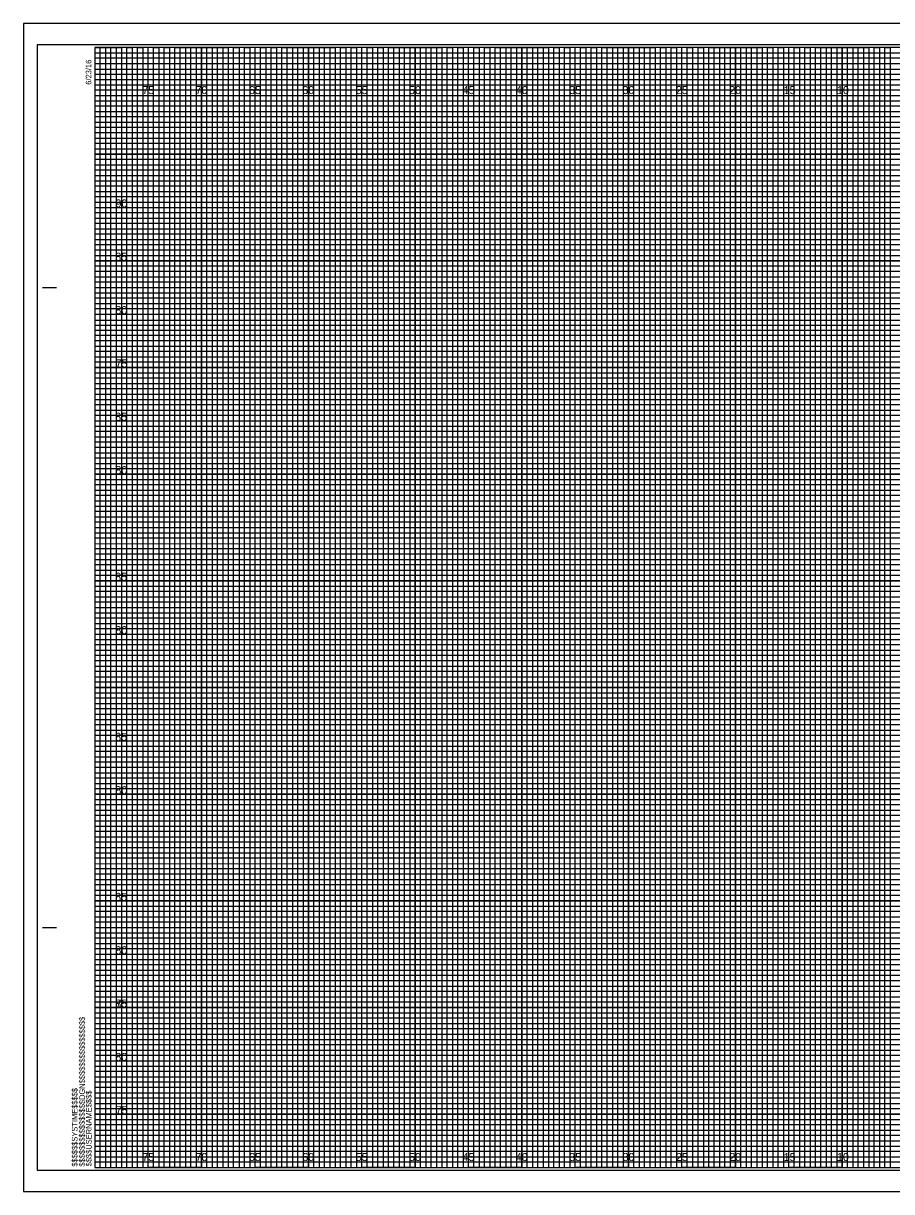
# Model space of a CAD drawing. Extents: x -7 to 182, y -2 to 1647.
# Drawn here: x -6.7 to 74.6, y 107.7 to 217.2 of the extents above; entities that cross this region are included whole.
import ezdxf

# ---------------------------------------------------------------- set-up
doc = ezdxf.new("R2010")
doc.units = 0
for name, color, linetype in [('Exist Cross Section Cell', 7, 'Continuous'), ('Exist XS Ground Line', 7, 'Continuous'), ('Prop CMT Pvmt Course 3', 7, 'Continuous'), ('Prop CMT Pvmt Wedge Surface 1', 7, 'Continuous'), ('Prop CMT Pvmt Wedge Surface 2', 7, 'Continuous'), ('Prop CMT Pvmt Wedge Surface 3', 7, 'Continuous'), ('Prop CMT Shld Paved Course 1', 7, 'Continuous'), ('Prop CMT Shld Paved Course 2', 7, 'Continuous'), ('Prop CMT Shld Paved Course 3', 7, 'Continuous'), ('Prop CMT Slope Grass', 7, 'Continuous'), ('Prop CMT Subgrade Earthwork', 7, 'Continuous')]:
    doc.layers.add(name, color=color, linetype=linetype)

msp = doc.modelspace()

# ---------------------------------------------------------------- linework, layer by layer
at = {"layer": 'Exist XS Ground Line'}
for p, q in [((5, 215), (0, 215)), ((5, 110), (5, 215)), ((15, 215), (10, 215)), ((10, 215), (10, 110)), ((15, 110), (15, 215)), ((25, 215), (20, 215)), ((20, 215), (20, 110)), ((25, 110), (25, 215)), ((35, 215), (30, 215)), ((30, 215), (30, 110)), ((35, 110), (35, 215)), ((45, 215), (40, 215)), ((40, 215), (40, 110)), ((45, 110), (45, 215)), ((55, 215), (50, 215)), ((50, 215), (50, 110)), ((55, 110), (55, 215)), ((65, 215), (60, 215)), ((60, 215), (60, 110)), ((65, 110), (65, 215)), ((75, 215), (70, 215)), ((70, 215), (70, 110)), ((10, 110), (5, 110)), ((20, 110), (15, 110)), ((30, 110), (25, 110)), ((40, 110), (35, 110)), ((50, 110), (45, 110)), ((60, 110), (55, 110)), ((70, 110), (65, 110))]:
    msp.add_line(p, q, dxfattribs=at)
for points in [[(0, 210), (160, 210), (160, 205), (0, 205)], [(0, 200), (160, 200), (160, 195), (0, 195)], [(0, 190), (160, 190), (160, 185), (0, 185)], [(0, 180), (160, 180), (160, 175), (0, 175)], [(0, 170), (160, 170), (160, 165), (0, 165)], [(0, 160), (160, 160), (160, 155), (0, 155)], [(0, 150), (160, 150), (160, 145), (0, 145)], [(0, 140), (160, 140), (160, 135), (0, 135)], [(0, 130), (160, 130), (160, 125), (0, 125)], [(0, 120), (160, 120), (160, 115), (0, 115)]]:
    msp.add_lwpolyline(points, dxfattribs=at)
at = {"layer": 'Prop CMT Pvmt Course 3'}
msp.add_lwpolyline([(-6.7, 107.75), (161.65, 107.75), (161.65, 217.25), (-6.7, 217.25)], close=True, dxfattribs=at)
at = {"layer": 'Prop CMT Pvmt Wedge Surface 1'}
for p, q in [((0, 214.5), (130, 214.5)), ((130, 213.99), (0, 213.99)), ((0, 213.99), (0, 213.5)), ((0, 213.5), (130, 213.5)), ((130, 212.94), (0, 212.94)), ((0, 212.94), (0, 212)), ((0, 212), (160, 212))]:
    msp.add_line(p, q, dxfattribs=at)
for points in [[(0, 211.5), (135, 211.5), (160, 211.5), (160, 211), (0, 211)], [(0, 210.5), (160, 210.5), (160, 209.5), (0, 209.5)], [(0, 209), (160, 209), (160, 208.5), (0, 208.49)], [(0, 208), (160, 208), (160, 207), (0, 207)], [(0, 206.5), (160, 206.5), (160, 206), (0, 206)], [(0, 205.5), (160, 205.5), (160, 204.5), (0, 204.5)], [(0, 204), (160, 204), (160, 203.5), (0, 203.5)], [(0, 203), (160, 203), (160, 202), (0, 202)], [(0, 201.5), (160, 201.5), (160, 201), (0, 201)], [(0, 200.5), (160, 200.5), (160, 199.5), (0, 199.5)], [(0, 199), (160, 199), (160, 198.5), (0, 198.5)], [(0, 198), (160, 198), (160, 196.97), (160, 196.5), (160, 196), (0, 196)], [(0, 197), (160, 197), (160, 196.5), (0, 196.5)], [(0, 195.5), (160, 195.5), (160, 194.5), (0, 194.52)], [(0, 194.52), (160, 194.5), (160, 194), (0, 194)], [(0, 193.5), (160, 193.5), (160, 193), (0, 193)], [(0, 192), (160, 192), (160, 191.5), (0, 191.5)], [(0, 191), (160, 191), (160, 190.5), (0, 190.5)], [(-0.04, 189.44), (160, 189.44), (160, 188.94), (-0.04, 188.94)], [(0, 188.5), (160, 188.5), (160, 188), (0, 188)], [(0, 187), (160, 187), (160, 186.5), (0, 186.5)], [(0, 186), (160, 186), (160, 185.5), (0, 185.5)], [(0, 184.5), (160, 184.5), (160, 184), (0, 184)], [(0, 183.5), (160, 183.5), (160, 183), (0, 183)], [(0, 182), (160, 182), (160, 181.5), (0, 181.5)], [(0, 181), (160, 181), (160, 180.5), (0, 180.5)], [(0, 179.5), (160, 179.5), (160, 178.99), (0, 179)], [(0, 178.5), (160, 178.5), (160, 178), (0, 178)], [(0, 177), (160, 177), (160, 176.5), (0, 176.5)], [(0, 176), (160, 176), (160, 175.5), (0, 175.5)], [(0, 174.5), (160, 174.5), (160, 174), (0, 174)], [(0, 173.5), (160, 173.5), (160, 173), (0, 173)], [(0, 172), (160, 172), (160, 171.5), (0, 171.5)], [(0, 171), (160, 171), (160, 170.5), (0, 170.5)], [(0, 169.5), (160, 169.5), (160, 169), (0, 169)], [(0, 168.5), (160.03, 168.46), (160, 168), (0, 168)], [(0, 167), (160, 167), (160, 166.5), (0, 166.5)], [(0, 166), (160, 166), (160, 165.5), (0, 165.5)], [(0, 164.5), (160, 164.5), (160, 164), (0, 164)], [(0, 163.5), (160, 163.5), (160, 163), (0, 163)], [(0, 162), (160, 162), (160, 161.5), (0, 161.5)], [(0, 161), (160, 161), (160, 160.5), (0, 160.5)], [(0, 159.5), (160, 159.5), (160, 159), (0, 159)], [(0, 158.5), (160, 158.5), (160, 158), (0, 158)], [(0, 157), (160, 157), (160, 156.5), (0, 156.5)], [(0, 156), (160, 156), (160, 155.5), (0, 155.5)], [(0, 154.5), (160, 154.5), (160, 154), (0, 154)], [(0, 153.5), (160, 153.5), (160, 153), (0, 153)], [(0, 152), (160, 152), (160, 151.5), (0, 151.5)], [(0, 151), (160, 151), (160, 150.5), (0, 150.5)], [(0, 149.5), (160, 149.5), (160, 148.99), (0, 149)], [(0, 148.5), (160, 148.5), (160, 148), (0, 148)], [(0, 147), (160, 147), (160, 146.5), (0, 146.5)], [(0, 146), (160, 146), (160, 145.5), (0, 145.5)], [(0, 144.5), (160, 144.5), (160, 144), (0, 144)], [(0, 143.5), (160, 143.5), (160, 143), (0, 143)], [(0, 142), (160, 142), (160, 141.5), (0, 141.5)], [(0, 141), (160, 141), (160, 140.5), (0, 140.5)], [(0, 139.5), (160, 139.5), (160, 139), (0, 139)], [(0, 138.5), (160.03, 138.46), (160, 138), (0, 138)], [(0, 137), (160, 137), (160, 136.5), (0, 136.5)], [(0, 136), (160, 136), (160, 135.5), (0, 135.5)], [(0, 134.5), (160, 134.5), (160, 134), (0, 134)], [(0, 133.5), (160, 133.5), (160, 133), (0, 133)], [(0, 132), (160, 132), (160, 131.5), (0, 131.5)], [(0, 131), (160, 131), (160, 130.5), (0, 130.5)], [(0, 129.5), (160, 129.5), (160, 129), (0, 129)], [(0, 128.5), (160, 128.5), (160, 128), (0, 128)], [(0, 127), (160, 127), (160, 126.5), (0, 126.5)], [(0, 126), (160, 126), (160, 125.5), (0, 125.5)], [(0, 124.5), (160, 124.5), (160, 124), (0, 124)], [(0, 123.5), (160, 123.5), (160, 123), (0, 123)], [(0, 122), (160, 122), (160, 121.5), (0, 121.5)], [(0, 121), (160, 121), (160, 120.5), (0, 120.5)], [(0, 119.5), (160, 119.5), (160, 119), (0, 119)], [(0, 118.5), (160, 118.5), (160, 118), (0, 118)], [(0, 117), (160, 117), (160, 116.5), (0, 116.5)], [(0, 116), (160, 116), (160, 115.5), (0, 115.5)], [(0, 114.5), (160, 114.5), (160, 114), (0, 114)], [(0, 113.5), (160, 113.5), (160, 113), (0, 113)], [(0, 112), (160, 112), (160, 111.5), (0, 111.5)], [(0, 111), (160, 111), (160, 110.5), (0, 110.5)]]:
    msp.add_lwpolyline(points, dxfattribs=at)
at = {"layer": 'Prop CMT Pvmt Wedge Surface 2'}
for p, q in [((-4.9, 192.5), (-3.65, 192.5)), ((-4.85, 192.5), (-3.6, 192.5)), ((-4.9, 132.5), (-3.65, 132.5)), ((-4.85, 132.5), (-3.6, 132.5)), ((0, 110), (0, 110)), ((0, 110), (0, 110)), ((0, 110), (0, 110)), ((0, 110), (0, 110)), ((0, 110), (0, 110)), ((0, 110), (0, 110)), ((0, 110), (0, 110))]:
    msp.add_line(p, q, dxfattribs=at)
msp.add_lwpolyline([(160, 215), (0, 215), (0, 110), (160, 110)], close=True, dxfattribs=at)
at = {"layer": 'Prop CMT Pvmt Wedge Surface 3'}
for points in [[(0, 110), (0.5, 110), (0.5, 215), (1, 215), (1, 110)], [(1, 110), (1.5, 110), (1.5, 215), (2, 215), (2, 110)], [(2.5, 110), (3, 110), (3, 215), (3.5, 215), (3.5, 110)], [(3.5, 110), (4, 110), (4, 215), (4.5, 215), (4.5, 110)], [(5, 110), (5.5, 110), (5.5, 215), (6, 215), (6, 110)], [(6, 110), (6.5, 110), (6.5, 215), (7, 215), (7, 110)], [(7.5, 110), (8, 110), (8, 215), (8.5, 215), (8.5, 110)], [(8.5, 110), (9, 110), (9, 215), (9.5, 215), (9.5, 110)], [(10, 110), (10.5, 110), (10.5, 215), (11, 215), (11, 110)], [(11, 110), (11.5, 110), (11.5, 215), (12, 215), (12, 110)], [(12.5, 110), (13, 110), (13, 215), (13.5, 215), (13.5, 110)], [(13.5, 110), (14, 110), (14, 215), (14.5, 215), (14.5, 110)], [(15, 110), (15.5, 110), (15.5, 215), (16, 215), (16, 110)], [(16, 110), (16.5, 110), (16.5, 215), (17, 215), (17, 110)], [(17.5, 110), (18, 110), (18, 215), (18.5, 215), (18.5, 110)], [(18.5, 110), (19, 110), (19, 215), (19.5, 215), (19.5, 110)], [(20, 110), (20.5, 110), (20.5, 215), (21, 215), (21, 110)], [(21, 110), (21.5, 110), (21.5, 215), (22, 215), (22, 110)], [(22.5, 110), (23, 110), (23, 215), (23.5, 215), (23.5, 110)], [(23.5, 110), (24, 110), (24, 215), (24.5, 215), (24.5, 110)], [(25, 110), (25.5, 110), (25.5, 215), (26, 215), (26, 110)], [(26, 110), (26.5, 110), (26.5, 215), (27, 215), (27, 110)], [(27.5, 110), (28, 110), (28, 215), (28.5, 215), (28.5, 110)], [(28.5, 110), (29, 110), (29, 215), (29.5, 215), (29.5, 110)], [(30, 110), (30.5, 110), (30.5, 215), (31, 215), (31, 110)], [(31, 110), (31.5, 110), (31.5, 215), (32, 215), (32, 110)], [(32.5, 110), (33, 110), (33, 215), (33.5, 215), (33.5, 110)], [(33.5, 110), (34, 110), (34, 215), (34.5, 215), (34.5, 110)], [(35, 110), (35.5, 110), (35.5, 215), (36, 215), (36, 110)], [(36, 110), (36.5, 110), (36.5, 215), (37, 215), (37, 110)], [(37.5, 110), (38, 110), (38, 215), (38.5, 215), (38.5, 110)], [(38.5, 110), (39, 110), (39, 215), (39.5, 215), (39.5, 110)], [(40, 110), (40.5, 110), (40.5, 215), (41, 215), (41, 110)], [(41, 110), (41.5, 110), (41.5, 215), (42, 215), (42, 110)], [(42.5, 110), (43, 110), (43, 215), (43.5, 215), (43.5, 110)], [(43.5, 110), (44, 110), (44, 215), (44.5, 215), (44.5, 110)], [(45, 110), (45.5, 110), (45.5, 215), (46, 215), (46, 110)], [(46, 110), (46.5, 110), (46.5, 215), (47, 215), (47, 110)], [(47.5, 110), (48, 110), (48, 215), (48.5, 215), (48.5, 110)], [(48.5, 110), (49, 110), (49, 215), (49.5, 215), (49.5, 110)], [(50, 110), (50.5, 110), (50.5, 215), (51, 215), (51, 110)], [(51, 110), (51.5, 110), (51.5, 215), (52, 215), (52, 110)], [(52.5, 110), (53, 110), (53, 215), (53.5, 215), (53.5, 110)], [(53.5, 110), (54, 110), (54, 215), (54.5, 215), (54.5, 110)], [(55, 110), (55.5, 110), (55.5, 215), (56, 215), (56, 110)], [(56, 110), (56.5, 110), (56.5, 215), (57, 215), (57, 110)], [(57.5, 110), (58, 110), (58, 215), (58.5, 215), (58.5, 110)], [(58.5, 110), (59, 110), (59, 215), (59.5, 215), (59.5, 110)], [(60, 110), (60.5, 110), (60.5, 215), (61, 215), (61, 110)], [(61, 110), (61.5, 110), (61.5, 215), (62, 215), (62, 110)], [(62.5, 110), (63, 110), (63, 215), (63.5, 215), (63.5, 110)], [(63.5, 110), (64, 110), (64, 215), (64.5, 215), (64.5, 110)], [(65, 110), (65.5, 110), (65.5, 215), (66, 215), (66, 110)], [(66, 110), (66.5, 110), (66.5, 215), (67, 215), (67, 110)], [(67.5, 110), (68, 110), (68, 215), (68.5, 215), (68.5, 110)], [(68.5, 110), (69, 110), (69, 215), (69.5, 215), (69.5, 110)], [(70, 110), (70.5, 110), (70.5, 215), (71, 215), (71, 110)], [(71, 110), (71.5, 110), (71.5, 215), (72, 215), (72, 110)], [(72.5, 110), (73, 110), (73, 215), (73.5, 215), (73.5, 110)], [(73.5, 110), (74, 110), (74, 215), (74.5, 215), (74.5, 110)]]:
    msp.add_lwpolyline(points, dxfattribs=at)
at = {"layer": 'Prop CMT Shld Paved Course 1'}
for p, q in [((5, 110), (5, 215)), ((10, 110), (10, 215)), ((15, 110), (15, 215)), ((20, 110), (20, 215)), ((25, 110), (25, 215)), ((30, 110), (30, 215)), ((35, 110), (35, 215)), ((40, 110), (40, 215)), ((45, 110), (45, 215)), ((50, 110), (50, 215)), ((55, 110), (55, 215)), ((60, 110), (60, 215)), ((65, 110), (65, 215)), ((70, 110), (70, 215)), ((0, 210), (160, 210)), ((0, 205), (160, 205)), ((0, 200), (160, 200)), ((0, 195), (160, 195)), ((0, 190), (160, 190)), ((0, 185), (160, 185)), ((0, 180), (160, 180)), ((0, 175), (160, 175)), ((0, 170), (160, 170)), ((0, 165), (160, 165)), ((0, 160), (160, 160)), ((0, 155), (160, 155)), ((0, 150), (160, 150)), ((0, 145), (160, 145)), ((0, 140), (160, 140)), ((0, 135), (160, 135)), ((0, 130), (160, 130)), ((0, 125), (160, 125)), ((0, 120), (160, 120)), ((0, 115), (160, 115))]:
    msp.add_line(p, q, dxfattribs=at)
at = {"layer": 'Prop CMT Shld Paved Course 2'}
for p, q in [((161.65, 217.25), (-6.7, 217.25)), ((-6.7, 217.25), (-6.7, 107.75)), ((-6.7, 107.75), (161.65, 107.75))]:
    msp.add_line(p, q, dxfattribs=at)
at = {"layer": 'Prop CMT Slope Grass'}
msp.add_lwpolyline([(-5.4, 109.75), (161.2, 109.75), (161.2, 215.25), (-5.4, 215.25)], close=True, dxfattribs=at)
at = {"layer": 'Prop CMT Subgrade Earthwork'}
for points in [[(0, 215), (2.5, 215), (2.5, 110), (7.5, 110), (7.5, 215), (12.5, 215), (12.5, 110), (17.5, 110), (17.5, 215), (22.5, 215), (22.5, 110), (27.5, 110), (27.5, 215), (32.5, 215), (32.5, 110), (37.5, 110), (37.5, 215), (42.5, 215), (42.5, 110), (47.5, 110), (47.5, 215), (52.5, 215), (52.5, 110), (57.5, 110), (57.5, 215), (62.5, 215), (62.5, 110), (67.5, 110), (67.5, 215), (72.5, 215), (72.5, 110), (77.5, 110)], [(0, 212.5), (137.5, 212.5)], [(0, 202.5), (160, 202.5), (160, 207.5), (0, 207.5)], [(0, 192.5), (160, 192.5), (160, 197.5), (0, 197.5)], [(0, 182.5), (160, 182.5), (160, 187.5), (0, 187.5)], [(0, 172.5), (160, 172.5), (160, 177.5), (0, 177.5)], [(0, 162.5), (160, 162.5), (160, 167.5), (0, 167.5)], [(0, 152.5), (160, 152.5), (160, 157.5), (0, 157.5)], [(0, 142.5), (160, 142.5), (160, 147.5), (0, 147.5)], [(0, 132.5), (160, 132.5), (160, 137.5), (0, 137.5)], [(0, 122.5), (160, 122.5), (160, 127.5), (0, 127.5)], [(0, 112.5), (160, 112.5), (160, 117.5), (0, 117.5)]]:
    msp.add_lwpolyline(points, dxfattribs=at)

# ---------------------------------------------------------------- texts
at = {"layer": 'Exist Cross Section Cell'}
for s, p in [('75', (4.44, 210.62)), ('70', (9.43, 210.62)), ('65', (14.44, 210.62)), ('60', (19.43, 210.62)), ('55', (24.44, 210.62)), ('50', (29.43, 210.62)), ('45', (34.44, 210.62)), ('40', (39.43, 210.62)), ('35', (44.44, 210.62)), ('30', (49.43, 210.62)), ('25', (54.44, 210.62)), ('20', (59.43, 210.62)), ('15', (64.53, 210.62)), ('10', (69.52, 210.62)), ('75', (4.44, 110.62)), ('70', (9.43, 110.62)), ('65', (14.44, 110.62)), ('60', (19.43, 110.62)), ('55', (24.44, 110.62)), ('50', (29.43, 110.62)), ('45', (34.44, 110.62)), ('40', (39.43, 110.62)), ('35', (44.44, 110.62)), ('30', (49.43, 110.62)), ('25', (54.44, 110.62)), ('20', (59.43, 110.62)), ('15', (64.53, 110.62)), ('10', (69.52, 110.62))]:
    msp.add_text(s, height=0.75, dxfattribs=at).set_placement(p)
at = {"layer": 'Prop CMT Pvmt Wedge Surface 2'}
for s, p in [('6/23/16', (-0.33, 211.5)), ('$$$$$$$$$$$$$$$$DGN$$$$$$$$$$$$$$$$', (-0.94, 110.09)), ('$$$$$$SYSTIME$$$$$', (-1.63, 110.09)), ('$$$$USERNAME$$$$', (-0.31, 110.12))]:
    msp.add_text(s, height=0.525, rotation=90, dxfattribs=at).set_placement(p)
at = {"layer": 'Prop CMT Shld Paved Course 3'}
for s, p in [('90', (1.93, 200)), ('85', (1.91, 195)), ('80', (1.92, 190)), ('75', (1.94, 185)), ('85', (1.91, 180)), ('80', (1.92, 175)), ('85', (1.91, 165)), ('80', (1.92, 160)), ('85', (1.91, 150)), ('80', (1.92, 145)), ('85', (1.91, 135)), ('80', (1.92, 130)), ('85', (1.91, 125)), ('75', (1.94, 125)), ('80', (1.92, 120)), ('75', (1.94, 115))]:
    msp.add_text(s, height=0.75, dxfattribs=at).set_placement(p)

doc.saveas('drawing.dxf')
